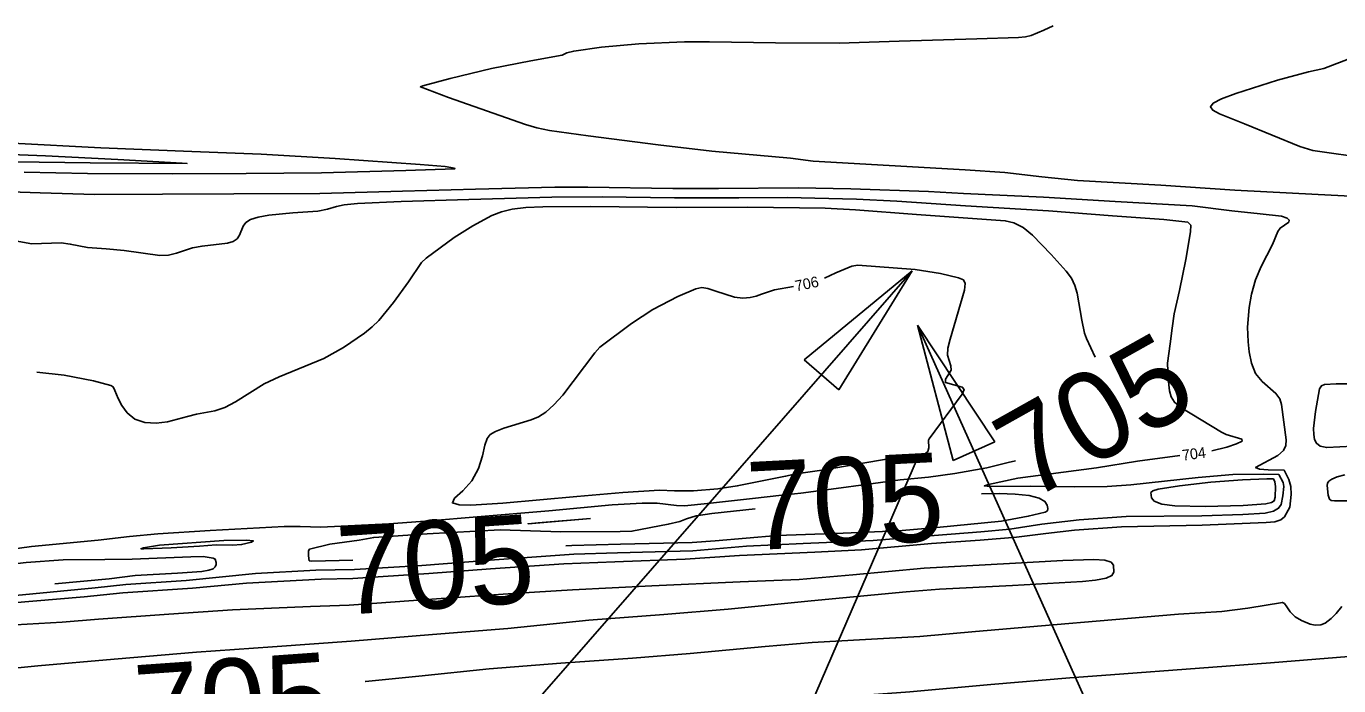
# Model space of a CAD drawing. Extents: x -291892836 to 2945206, y -477993085 to 1832792.
# Drawn here: x 1852246.4 to 1852737.2, y 543667.6 to 543914.3 of the extents above; entities that cross this region are included whole.
import ezdxf

# ---------------------------------------------------------------- set-up
doc = ezdxf.new("R2010")
doc.units = 0
for name, color, linetype in [('DT_X_Contour_Minor', 7, 'Continuous'), ('DT_X_Terrain_Ground_Line', 7, 'Continuous'), ('Level 19', 7, 'Continuous'), ('Level 40', 7, 'Continuous')]:
    doc.layers.add(name, color=color, linetype=linetype)

msp = doc.modelspace()

# ---------------------------------------------------------------- linework, layer by layer
at = {"layer": 'DT_X_Contour_Minor'}
for points in [[(1852761.34, 543849.72), (1852729.51, 543851.31), (1852698.32, 543853), (1852670.62, 543854.88), (1852639.51, 543856.57), (1852626.18, 543857.93), (1852612.33, 543859.52), (1852597.46, 543860.55), (1852569.12, 543862.12), (1852540.73, 543863.81), (1852532.23, 543864.89), (1852502.74, 543867.51), (1852482.66, 543869.94), (1852456.52, 543873.26), (1852442.11, 543875.26), (1852437.3, 543876.26), (1852433.06, 543877.54), (1852404.29, 543887.62), (1852393.82, 543891.59), (1852394.67, 543891.93), (1852404.96, 543894.67), (1852420.42, 543898.4), (1852435.14, 543901.3), (1852446.76, 543903.5), (1852448.61, 543904.34), (1852451.12, 543904.95), (1852461.46, 543906.48), (1852475.43, 543907.7), (1852492.5, 543908.39), (1852501.88, 543908.41), (1852526.63, 543908.07), (1852550.34, 543907.97), (1852572.82, 543908.64), (1852601.91, 543909.54), (1852617.49, 543910), (1852620.03, 543910.28), (1852622.17, 543910.85), (1852626.95, 543912.84), (1852630.43, 543914.46)], [(1852748.55, 543864.82), (1852727.48, 543867.84), (1852722.61, 543869.29), (1852701.91, 543877.76), (1852692.63, 543881.52), (1852690.09, 543882.86), (1852689.23, 543884.1), (1852690.26, 543885.48), (1852693.34, 543887.12), (1852698.68, 543889.15), (1852714.25, 543894.07), (1852725.89, 543897.17), (1852731.62, 543898.41), (1852742.4, 543902.56)], [(1852245.61, 543859.71), (1852269.25, 543859.24), (1852301.23, 543859.02), (1852328.59, 543859.18), (1852356.86, 543859.48), (1852388.32, 543860.3), (1852406.69, 543860.95), (1852406.53, 543861.21), (1852403.03, 543861.76), (1852393.65, 543862.51), (1852361.86, 543864.8), (1852334.19, 543866.4), (1852308.36, 543867.4), (1852274.35, 543868.82), (1852241.2, 543870.48)], [(1852241.8, 543863.49), (1852270.29, 543863.13), (1852306.55, 543862.91), (1852304.76, 543863.11), (1852280.62, 543864.39), (1852253.58, 543865.76), (1852221.2, 543867.09)], [(1852225.18, 543852.77), (1852251.56, 543851.93), (1852272.02, 543851.37), (1852297.33, 543851.43), (1852324.02, 543851.52), (1852356.14, 543851.69), (1852387.09, 543852.57), (1852414.34, 543853.27), (1852444.1, 543854.06), (1852456.41, 543854.07), (1852488.24, 543853.55), (1852505.25, 543853.55), (1852535.1, 543853.84), (1852554.77, 543853.44), (1852583.8, 543852.51), (1852596.92, 543851.76), (1852626.79, 543850.29), (1852653.64, 543848.75), (1852682.38, 543847.14), (1852697.21, 543845.23), (1852707.86, 543844.08), (1852715.77, 543843.17), (1852717.86, 543842.5), (1852718.72, 543841.74), (1852718.58, 543841), (1852715.27, 543838.77), (1852714.47, 543837.43), (1852712.49, 543832.67), (1852708.15, 543824.4), (1852706.02, 543819.36), (1852704.57, 543814.09), (1852703.72, 543809.09), (1852703.12, 543801.77), (1852703.34, 543796.26), (1852703.74, 543792.47), (1852704.57, 543788.28), (1852706.14, 543784.4), (1852708.58, 543781.37), (1852713.71, 543776.92), (1852715.15, 543774.85), (1852715.82, 543772.84), (1852717.53, 543759.62), (1852717.44, 543757.49), (1852716.59, 543755.53), (1852714.49, 543753.68)], [(1852359.04, 543845.87), (1852362.4, 543846.89), (1852365.29, 543847.44), (1852370.27, 543847.95), (1852386.58, 543848.73), (1852411.95, 543849.48), (1852442.93, 543850.34), (1852461.75, 543850.4), (1852488.86, 543850.04), (1852512.92, 543850.14), (1852530.99, 543850.18), (1852556.89, 543849.62), (1852571.94, 543848.89), (1852597.65, 543847.15), (1852628.68, 543845.21), (1852652.59, 543843.36), (1852671.84, 543841.92), (1852680.75, 543840.94), (1852681.86, 543839.84), (1852681.72, 543837.31), (1852680.07, 543827.06), (1852677.64, 543815.39), (1852675.62, 543806.75), (1852674.95, 543801.4), (1852674.17, 543795.49), (1852673.22, 543788.31), (1852673.44, 543782.56), (1852673.98, 543777.86), (1852674.54, 543775.68), (1852675.85, 543773.62), (1852678.18, 543771.68), (1852693.31, 543762.47), (1852695.09, 543761.62), (1852700.95, 543759.88), (1852701.04, 543759.11), (1852698.93, 543758.03), (1852695.32, 543756.82), (1852689.69, 543755.48)], [(1852233.9, 543835.54), (1852248.54, 543832.94), (1852259.47, 543833.23), (1852262.85, 543832.81), (1852269.32, 543831.53), (1852276.26, 543830.97), (1852283.07, 543830.41), (1852296.35, 543828.56), (1852299.56, 543828.7), (1852302.54, 543829.42), (1852308.63, 543831.41), (1852312.13, 543832.04), (1852321.71, 543833.07), (1852323.78, 543833.69), (1852325.23, 543834.69), (1852326.15, 543836.15), (1852327.5, 543839.52), (1852328.56, 543840.92), (1852330.32, 543842.03), (1852333.1, 543842.91), (1852337.06, 543843.58), (1852346.11, 543844.44), (1852355.42, 543845.14), (1852359.04, 543845.87)], [(1852250.34, 543784.89), (1852260.57, 543783.76), (1852271.61, 543781.64), (1852277.97, 543779.88), (1852278.91, 543779.36), (1852279.47, 543778.08), (1852280.78, 543775.04), (1852282.14, 543772.45), (1852284.17, 543769.65), (1852287.03, 543767.36), (1852290.78, 543766.11), (1852295.02, 543765.83), (1852299.27, 543766.28), (1852306.66, 543768.3), (1852310.03, 543769.23), (1852316.86, 543770.43), (1852320.6, 543771.64), (1852324.66, 543773.76), (1852335.39, 543780.57), (1852340.98, 543783.1), (1852357.74, 543790.02), (1852365.03, 543794.12), (1852372.84, 543799.42), (1852375.78, 543801.81), (1852378.28, 543804.24), (1852383.72, 543810.88), (1852389.33, 543818.68), (1852394.21, 543825.94), (1852395.93, 543827.54), (1852406.45, 543835.27), (1852413.38, 543839.66), (1852420.52, 543843.5), (1852424.06, 543844.85), (1852428.13, 543845.82), (1852433.17, 543846.42), (1852439.54, 543846.73), (1852457.34, 543846.82), (1852489.48, 543846.53), (1852516.22, 543846.65), (1852545.14, 543846.16), (1852556.53, 543845.56), (1852579.3, 543843.86), (1852612.51, 543841.5), (1852615.69, 543840.7), (1852619.14, 543838.99), (1852622.71, 543836.12), (1852629.62, 543828.88), (1852635.22, 543822.71), (1852637.21, 543819.98), (1852638.54, 543817.25), (1852639.39, 543814.37), (1852641.15, 543804.37), (1852642.12, 543799.45), (1852642.82, 543797.52), (1852646.13, 543790.52)], [(1852533.28, 543816.93), (1852526.2, 543815.62), (1852521.31, 543814.01), (1852519.35, 543813.3), (1852517.06, 543812.76), (1852514.34, 543812.58), (1852511.21, 543812.95), (1852504.31, 543815.19), (1852501.3, 543816.18), (1852498.98, 543816.5), (1852496.78, 543816.08), (1852490.1, 543813.16), (1852480.75, 543808.29), (1852472.7, 543803.05), (1852460.93, 543794.25), (1852459.05, 543792.08), (1852447.08, 543776.22), (1852443.75, 543772.63), (1852440.67, 543769.88), (1852437.93, 543768.15), (1852435.25, 543767.09), (1852424.97, 543763.89), (1852421.91, 543762.7), (1852419.94, 543761.59), (1852418.77, 543760.07), (1852417.95, 543757.53), (1852417, 543753.58), (1852415.51, 543748.87), (1852413.07, 543744.26), (1852409.63, 543740.5), (1852406.6, 543737.75), (1852405.76, 543736.01), (1852408.24, 543735.25), (1852412.67, 543735.15), (1852424.67, 543735.85), (1852452.29, 543738.32), (1852469.54, 543739.86), (1852483.15, 543740.76), (1852488.8, 543740.44), (1852495.92, 543740.46), (1852505.03, 543741.24), (1852512.29, 543742.37), (1852530.36, 543745.97), (1852534.37, 543746.9), (1852544.72, 543748.39), (1852569.52, 543752.56), (1852579.2, 543753.36), (1852582.13, 543754.09), (1852583.58, 543755.25), (1852583.94, 543756.61), (1852583.84, 543759.4), (1852584, 543760.01), (1852596.39, 543776.69), (1852597.11, 543778.38), (1852596.39, 543779.33), (1852590.1, 543780.97), (1852590.21, 543782.21), (1852592.24, 543785.58), (1852592.17, 543787.27), (1852590.94, 543791.18), (1852591.07, 543793.86), (1852591.86, 543797.24), (1852597.2, 543815.58), (1852597.51, 543818.09), (1852596.84, 543819.41), (1852594.99, 543820.19), (1852588.24, 543821.74), (1852578.83, 543823.28), (1852557.4, 543824.9), (1852555.12, 543824.49), (1852549.12, 543822), (1852544.89, 543820.02)], [(1852757.06, 543757.9), (1852732.75, 543756.66), (1852730.32, 543757.24), (1852728.92, 543758.28), (1852728.19, 543759.72), (1852727.84, 543761.53), (1852727.78, 543763.8), (1852728.5, 543770.13), (1852730.07, 543778.66), (1852730.7, 543779.74), (1852731.91, 543780.25), (1852736.28, 543780.47), (1852740.44, 543780.55)], [(1852714.49, 543753.68), (1852706.08, 543749.26), (1852707.53, 543748.63), (1852710.79, 543748.37), (1852716.75, 543748.28), (1852718.56, 543744.74), (1852719.31, 543742.1), (1852719.36, 543739.18), (1852718.97, 543734.41), (1852718.27, 543733.28), (1852716.97, 543730.79), (1852715.57, 543729.64), (1852713.33, 543728.95), (1852710.04, 543728.61), (1852686.12, 543727.69), (1852655.97, 543726.99), (1852638.35, 543725.85), (1852627.64, 543724.59), (1852616.65, 543723.13), (1852603.06, 543722.09), (1852584.98, 543720.75), (1852558.74, 543718.44), (1852541.24, 543717.6), (1852513.08, 543716.35), (1852492.82, 543714.89), (1852466.45, 543713.98), (1852447.41, 543713.21), (1852420.03, 543711.34), (1852396.96, 543709.61), (1852368.51, 543707.76), (1852356.63, 543707.49), (1852328.76, 543705.98), (1852308.63, 543704.08), (1852282.47, 543702.32), (1852268.1, 543700.89), (1852240.06, 543698.45)], [(1852616.32, 543751.71), (1852613.54, 543751.08), (1852605.58, 543749.16), (1852593.62, 543746.97), (1852583.82, 543745.66), (1852573.24, 543744.63), (1852551.1, 543741.65), (1852536.07, 543739.59), (1852528.89, 543738.82), (1852518.03, 543737.69), (1852501.11, 543735.72), (1852492.56, 543734.92), (1852489.5, 543735.07), (1852482.28, 543735.88), (1852476.69, 543735.94), (1852465.5, 543735.22), (1852441.77, 543733.05), (1852415.03, 543730.76), (1852397.24, 543729.33), (1852382.04, 543728.11), (1852356.54, 543726.87), (1852348.8, 543727.1), (1852342.83, 543727.11), (1852315.16, 543725.72), (1852295.63, 543724.41), (1852285.03, 543723.43), (1852273.33, 543721.99), (1852248.38, 543719.72), (1852240.22, 543718.59)], [(1852677.83, 543753.67), (1852661.91, 543751.63), (1852646.61, 543749.09), (1852617.25, 543745.22), (1852606.18, 543742.89), (1852604.71, 543742.31), (1852606.6, 543742.11), (1852621.77, 543742.22), (1852638.32, 543741.95), (1852650.57, 543742.13), (1852659.47, 543742.7), (1852684.59, 543745.45), (1852697.59, 543746.59), (1852708.97, 543746.69), (1852714.8, 543746.64), (1852716.42, 543743.59), (1852716.69, 543742.17), (1852716.33, 543738.67), (1852715.62, 543735.45), (1852714.68, 543733.98), (1852712.81, 543732.85), (1852709.74, 543732.17), (1852701.36, 543731.64), (1852686.07, 543731.18), (1852657.77, 543730.87), (1852640.11, 543729.67), (1852626.18, 543728.02), (1852614.17, 543726.22), (1852603.31, 543725.21), (1852585.93, 543723.8), (1852563.05, 543721.87), (1852536.87, 543720.78), (1852515.7, 543719.76), (1852495.61, 543718.1), (1852467.53, 543717.29), (1852451.22, 543716.77), (1852421.53, 543714.67), (1852394.28, 543712.63), (1852369.14, 543711.12), (1852354.66, 543710.79), (1852332.11, 543709.54), (1852306.18, 543706.97), (1852283.69, 543705.43), (1852272.23, 543704.21), (1852242.33, 543701.36)], [(1852740.71, 543736.81), (1852735.66, 543736.75), (1852734.38, 543736.93), (1852733.7, 543737.35), (1852733.27, 543738.93), (1852732.86, 543742.45), (1852732.99, 543743.38), (1852733.52, 543744.16), (1852734.68, 543744.9), (1852736.65, 543745.71), (1852739.43, 543746.53)], [(1852712.85, 543744.99), (1852713.35, 543743.92), (1852713.58, 543742.07), (1852713.39, 543738.09), (1852713.02, 543736.74), (1852712.11, 543736.12), (1852709.91, 543735.6), (1852701.52, 543735.02), (1852687.22, 543734.66), (1852675.89, 543734.94), (1852670.99, 543735.54), (1852668.22, 543736.58), (1852667.14, 543737.83), (1852666.96, 543739.86), (1852667.66, 543740.5), (1852669.62, 543741.07), (1852677.72, 543742.36), (1852689.37, 543743.74), (1852701.23, 543744.66), (1852710.37, 543745.01), (1852712.85, 543744.99)], [(1852448.22, 543719.88), (1852450.42, 543720.04), (1852468.62, 543720.6), (1852495.39, 543721.2), (1852504.01, 543721.76), (1852527.22, 543723.74), (1852551.83, 543724.68), (1852572.51, 543725.57), (1852586.87, 543726.84), (1852611.12, 543729.2), (1852621.12, 543730.98), (1852627.48, 543732.48), (1852628.29, 543733.06), (1852628.36, 543733.88), (1852628.19, 543735.11), (1852627.36, 543736.53), (1852625.23, 543737.81), (1852621.39, 543738.72), (1852616.19, 543739.24), (1852610.2, 543739.45), (1852603.57, 543739.32)], [(1852518.96, 543733.79), (1852502.81, 543732.05), (1852496.97, 543731.19), (1852493.28, 543730.07), (1852490.77, 543729.08), (1852486.47, 543728.02), (1852472.87, 543725.41), (1852468.55, 543725.24), (1852446.29, 543725.19), (1852423.57, 543725.93), (1852396.38, 543724.44), (1852376.37, 543723.1), (1852370.91, 543722.11), (1852359.97, 543720.53), (1852352.32, 543718.68), (1852351.98, 543718.1), (1852351.9, 543716.17), (1852352.23, 543714.38), (1852353.23, 543714.23), (1852368.57, 543714.57)], [(1852457.44, 543730.13), (1852434.08, 543728.2), (1852437.81, 543728.56), (1852457.44, 543730.13)], [(1852296.24, 543720.24), (1852320.3, 543721.87), (1852328.64, 543722.09), (1852331.36, 543721.74), (1852330.69, 543721.3), (1852326.93, 543720.4), (1852323.52, 543720.23), (1852317.36, 543720.26), (1852311.13, 543719.85), (1852300.58, 543719.16), (1852290.34, 543718.76), (1852289.26, 543718.87), (1852290.19, 543719.18), (1852296.24, 543720.24)], [(1852221.66, 543672.23), (1852250.7, 543674.99), (1852279.29, 543677.56), (1852310.01, 543680.11), (1852338.49, 543682.2), (1852367.93, 543684.22), (1852398.3, 543686.77), (1852426.46, 543688.98), (1852456.81, 543692.13), (1852484.84, 543694.19), (1852508.85, 543696.26), (1852539.96, 543699.32), (1852575.45, 543702.71), (1852587.89, 543703.71), (1852615.16, 543705.13), (1852641.44, 543706.63), (1852646.23, 543707.09), (1852650.21, 543707.8), (1852652.4, 543708.81), (1852653.15, 543710.04), (1852652.99, 543712.71), (1852652.08, 543713.85), (1852649.74, 543714.61), (1852645.59, 543714.87), (1852634, 543714.46), (1852614.07, 543713.35), (1852582.15, 543711.6), (1852555.46, 543709.08), (1852535.38, 543707.34), (1852513.42, 543706.47), (1852480.38, 543704.91), (1852450.66, 543703.43), (1852428.3, 543702.09), (1852399.83, 543700.17), (1852367.11, 543697.69), (1852352.68, 543697.18), (1852323.48, 543696.01), (1852299.75, 543694.41), (1852273.38, 543692.49), (1852259.89, 543691.39), (1852229.13, 543689.58)], [(1852235.41, 543712.5), (1852246.42, 543713.76), (1852260.23, 543714.68), (1852275.76, 543714.82), (1852285.96, 543714.9), (1852307.91, 543715.82), (1852312.57, 543715.94), (1852316.36, 543715.36), (1852317.01, 543714.96), (1852317.36, 543713.76), (1852317.36, 543712.94), (1852317.09, 543712.08), (1852316.28, 543711.33), (1852314.68, 543710.78), (1852312.03, 543710.39), (1852302.97, 543709.77), (1852287.15, 543708.84), (1852277.36, 543707.65), (1852257.09, 543705.69)], [(1852373.11, 543669.2), (1852373.21, 543669.21), (1852393.2, 543671.14), (1852419.5, 543673.97), (1852446.33, 543675.99), (1852473.07, 543677.91), (1852494.66, 543679.61), (1852522.78, 543682.24), (1852540.35, 543683.83), (1852560.21, 543684.92), (1852580.56, 543686.04), (1852601.39, 543687.86), (1852626, 543690.04), (1852652.38, 543692.22), (1852677.33, 543694.39), (1852693.53, 543695.39), (1852703.2, 543696.59), (1852716.15, 543698.75), (1852716.87, 543698.4), (1852717.82, 543697.06), (1852719.03, 543695.25), (1852720.94, 543693.43), (1852723.27, 543691.99), (1852726.51, 543690.68), (1852728.36, 543690.28), (1852730.45, 543690.39), (1852732.16, 543691.01), (1852734.35, 543692.75), (1852736.3, 543694.62), (1852738.3, 543697.26)], [(1852740.93, 543678.48), (1852711.64, 543676.23), (1852685.12, 543674.22), (1852651.82, 543671.63), (1852636.62, 543670.58), (1852607.15, 543668.04), (1852576.86, 543665.34), (1852541.57, 543662.65), (1852520.13, 543661.11), (1852484.87, 543658.44), (1852454.26, 543656.05), (1852425.53, 543653.73), (1852393.18, 543651.03), (1852366.12, 543648.78), (1852336.94, 543646.35), (1852304.2, 543643.57), (1852273.93, 543641.07), (1852238.34, 543638.15)]]:
    msp.add_lwpolyline(points, dxfattribs=at)
at = {"layer": 'Level 40'}
for p, q in [((1852308.53, 543514.64), (1852577.68, 543822.73)), ((1852537.28, 543789.55), (1852577.68, 543822.73)), ((1852577.68, 543822.73), (1852550.21, 543778.25)), ((1852710.96, 543509.66), (1852579.71, 543802.42)), ((1852592.96, 543751.84), (1852579.71, 543802.42)), ((1852579.71, 543802.42), (1852608.63, 543758.87)), ((1852550.21, 543778.25), (1852537.28, 543789.55)), ((1852608.63, 543758.87), (1852592.96, 543751.84)), ((1852479.07, 543520.28), (1852580.11, 543753.54))]:
    msp.add_line(p, q, dxfattribs=at)

# ---------------------------------------------------------------- texts
at = {"layer": 'DT_X_Terrain_Ground_Line'}
for rotation, p in [(29.3079, (1852621.56, 543736.35)), (2.945, (1852516.73, 543718.23)), (3.9018, (1852363.81, 543694)), (4.0279, (1852288.12, 543642.25))]:
    msp.add_text('705', height=33, rotation=rotation, dxfattribs=at).set_placement(p)
at = {"layer": 'Level 19'}
for s, rotation, p in [('706', 11.8889, (1852534.33, 543815.08)), ('704', 7.6834, (1852678.88, 543751.78))]:
    msp.add_text(s, height=4, rotation=rotation, dxfattribs=at).set_placement(p)

doc.saveas('drawing.dxf')
